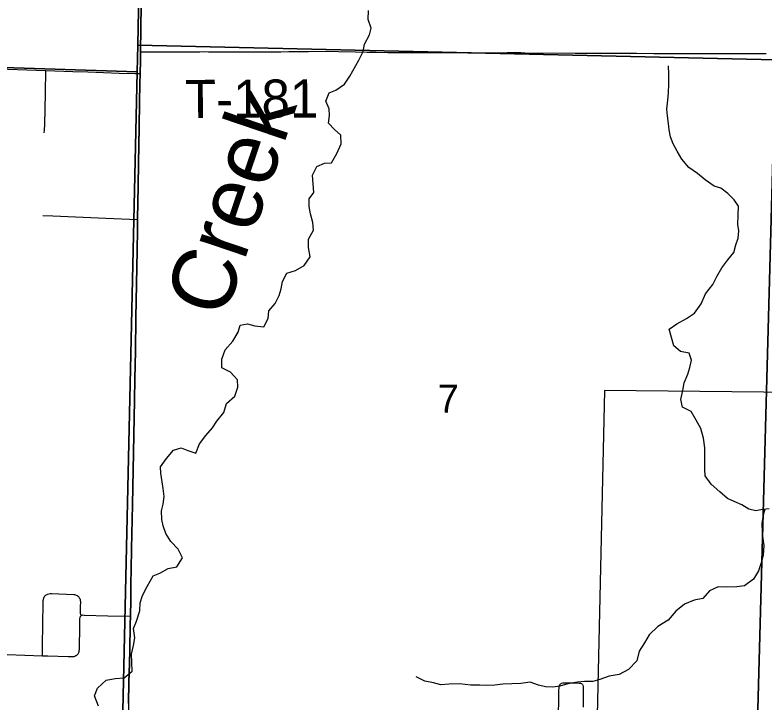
# Model space of a CAD drawing. Extents: x 0 to 34, y 0 to 22.
# Drawn here: x 5.615 to 6.731, y 18.619 to 19.643 of the extents above; entities that cross this region are included whole.
import ezdxf

# ---------------------------------------------------------------- set-up
doc = ezdxf.new("R2010")
doc.units = 0
for name, color, linetype in [('GM_X_Corporation', 7, 'Continuous'), ('GM_X_County_Road', 7, 'Continuous'), ('GM_X_Minor_River', 7, 'Continuous'), ('GM_X_Minor_River_Text', 7, 'Continuous'), ('GM_X_Section_Text', 7, 'Continuous'), ('GM_X_Township_Road', 7, 'Continuous'), ('GM_X_Township_Road_Text', 7, 'Continuous')]:
    doc.layers.add(name, color=color, linetype=linetype)

msp = doc.modelspace()

# ---------------------------------------------------------------- linework, layer by layer
at = {"layer": 'GM_X_Corporation'}
for points in [[(4.829, 20.5833), (5.8164, 20.5638), (5.7981, 19.5979), (5.7974, 19.5584), (4.8036, 19.5906)], [(5.8164, 20.5638), (6.788, 20.5454), (6.7486, 19.5865), (6.7472, 19.5762), (5.7981, 19.5979)], [(6.7472, 19.5762), (6.72, 18.5734), (5.7756, 18.586), (5.7974, 19.5584), (5.7981, 19.5979)], [(4.8036, 19.5906), (5.7974, 19.5584), (5.7756, 18.586), (5.7749, 18.5522), (4.7775, 18.5857)], [(6.7486, 19.5865), (7.7504, 19.5655), (7.7346, 18.5471), (6.72, 18.5734), (6.7472, 19.5762)]]:
    msp.add_lwpolyline(points, close=True, dxfattribs=at)
for points in [[(5.7845, 18.6185), (5.7851, 18.6508), (5.7858, 18.6782), (5.7862, 18.6987), (5.7867, 18.7359), (5.7871, 18.7491), (5.7877, 18.7725), (5.788, 18.7974), (5.7882, 18.8179), (5.7889, 18.849), (5.7901, 18.9142), (5.7933, 19.07), (5.7937, 19.1017), (5.7947, 19.1427), (5.7955, 19.1924), (5.7973, 19.2925), (5.7976, 19.3236), (5.7976, 19.3396), (5.7986, 19.3884), (5.7993, 19.4226), (5.8002, 19.4767), (5.8008, 19.5133), (5.8012, 19.5407), (5.8016, 19.5563), (5.8021, 19.5749), (5.8023, 19.5887), (5.8033, 19.6582)], [(5.8033, 19.6582), (5.8023, 19.5887), (5.8021, 19.5749), (5.8016, 19.5563), (5.8012, 19.5407), (5.8008, 19.5133), (5.8002, 19.4767), (5.7993, 19.4226), (5.7986, 19.3884), (5.7976, 19.3396), (5.7976, 19.3236), (5.7973, 19.2925), (5.7955, 19.1924), (5.7947, 19.1427), (5.7937, 19.1017), (5.7933, 19.07), (5.7901, 18.9142), (5.7889, 18.849), (5.7882, 18.8179), (5.788, 18.7974), (5.7877, 18.7725), (5.7871, 18.7491), (5.7867, 18.7359), (5.7862, 18.6987), (5.7858, 18.6782), (5.7851, 18.6508), (5.7845, 18.6185)], [(6.8851, 19.0796), (6.7293, 19.0817), (6.4924, 19.0846), (6.4812, 18.579)]]:
    msp.add_lwpolyline(points, dxfattribs=at)
at = {"layer": 'GM_X_County_Road'}
for points in [[(5.8025, 19.5881), (5.8035, 19.6576), (5.8043, 19.7024), (5.8052, 19.7639), (5.8058, 19.7975), (5.8061, 19.8255), (5.8063, 19.8478), (5.8071, 19.8907), (5.8076, 19.9268), (5.808, 19.9653), (5.8089, 20.0219), (5.8094, 20.0605), (5.8106, 20.1214), (5.8113, 20.1599), (5.8122, 20.1991), (5.813, 20.2432), (5.8138, 20.2811), (5.8144, 20.3128), (5.8159, 20.3769), (5.8167, 20.4278), (5.8179, 20.4919), (5.8193, 20.5613)], [(5.8018, 19.5558), (5.8023, 19.5743), (5.8025, 19.5881)], [(5.7979, 19.339), (5.7988, 19.3878), (5.7995, 19.422), (5.8005, 19.4761), (5.8011, 19.5128), (5.8014, 19.5401), (5.8018, 19.5558)], [(5.7874, 18.7485), (5.788, 18.772), (5.7882, 18.7968), (5.7885, 18.8173), (5.7891, 18.8484), (5.7903, 18.9136), (5.7935, 19.0695), (5.794, 19.1012), (5.7949, 19.1422), (5.7957, 19.1919), (5.7975, 19.2919), (5.7979, 19.323), (5.7979, 19.339)], [(5.6563, 18.6898), (5.6564, 18.6991), (5.6571, 18.7426), (5.6574, 18.7624), (5.6575, 18.7719), (5.6577, 18.7732), (5.6579, 18.7745), (5.6583, 18.7756), (5.6589, 18.777), (5.6601, 18.7787), (5.661, 18.7796), (5.6621, 18.7805), (5.6631, 18.7811), (5.6639, 18.7815), (5.6659, 18.782), (5.6678, 18.7822), (5.6698, 18.7821), (5.7028, 18.7811), (5.7042, 18.781), (5.7054, 18.7806), (5.7066, 18.7801), (5.7079, 18.7794), (5.709, 18.7786), (5.71, 18.7777), (5.7112, 18.776), (5.7118, 18.7748), (5.7122, 18.7735), (5.7125, 18.7719), (5.7128, 18.7703), (5.7126, 18.7627), (5.7125, 18.7531), (5.7127, 18.7517), (5.713, 18.7509), (5.7135, 18.75), (5.7138, 18.7494)], [(5.6563, 18.6898), (5.6643, 18.6896), (5.6947, 18.6885), (5.7003, 18.6885), (5.7017, 18.6885), (5.7034, 18.6888), (5.7047, 18.6892), (5.7062, 18.6899), (5.7074, 18.6906), (5.7083, 18.6916), (5.7093, 18.6927), (5.71, 18.6938), (5.7108, 18.6956), (5.7112, 18.6973), (5.7114, 18.6989), (5.7116, 18.7133), (5.7118, 18.7207), (5.7119, 18.7313), (5.7119, 18.7431), (5.712, 18.7447), (5.7123, 18.7466), (5.7126, 18.7476), (5.7132, 18.7486), (5.7138, 18.7494)], [(5.7138, 18.7494), (5.7149, 18.7501), (5.7156, 18.7503), (5.7169, 18.7504), (5.7184, 18.7503), (5.7538, 18.7493), (5.7874, 18.7485)], [(5.7843, 18.5826), (5.7844, 18.5925), (5.7847, 18.618), (5.7853, 18.6503), (5.7861, 18.6776), (5.7865, 18.6981), (5.787, 18.7354), (5.7874, 18.7485)], [(5.6014, 18.6915), (5.604, 18.6914), (5.6563, 18.6898)]]:
    msp.add_lwpolyline(points, dxfattribs=at)
at = {"layer": 'GM_X_Minor_River'}
for points in [[(6.1337, 19.5889), (6.1355, 19.5998), (6.143, 19.6133), (6.1456, 19.6235), (6.1409, 19.6361), (6.1416, 19.6498)], [(5.9231, 19.118), (5.9234, 19.1309), (5.9282, 19.1449), (5.9395, 19.1576), (5.9473, 19.1711), (5.9505, 19.1816), (5.9612, 19.1833), (5.9721, 19.1808), (5.9858, 19.1791), (5.9924, 19.1915), (5.993, 19.2028), (6.0024, 19.214), (6.0087, 19.2257), (6.0115, 19.2355), (6.0136, 19.2465), (6.0199, 19.2589), (6.0329, 19.2628), (6.0459, 19.2705), (6.0545, 19.2832), (6.0521, 19.2969), (6.052, 19.3095), (6.0594, 19.323), (6.0585, 19.3344), (6.0554, 19.347), (6.0533, 19.358), (6.0531, 19.3694), (6.0602, 19.3791), (6.0593, 19.3917), (6.058, 19.4046), (6.0647, 19.4178), (6.0762, 19.4225), (6.0864, 19.423), (6.0946, 19.4369), (6.1006, 19.4512), (6.1005, 19.4641), (6.0908, 19.4727), (6.0822, 19.4823), (6.0832, 19.4933), (6.083, 19.5032), (6.0779, 19.515), (6.0827, 19.5271), (6.0931, 19.5314), (6.1057, 19.5403), (6.1135, 19.5519), (6.1271, 19.5757), (6.1337, 19.5889)], [(6.7378, 18.9081), (6.7276, 18.9075), (6.718, 18.9051), (6.7075, 18.9076), (6.697, 18.9142), (6.6857, 18.919), (6.6755, 18.9237), (6.664, 18.9338), (6.6513, 18.9451), (6.6424, 18.9574), (6.6419, 18.9669), (6.6421, 18.9771), (6.6419, 18.9866), (6.6421, 18.9992), (6.6397, 19.0133), (6.6358, 19.0277), (6.6289, 19.04), (6.6215, 19.0531), (6.6088, 19.0594), (6.6063, 19.0712), (6.6093, 19.0844), (6.6114, 19.0958), (6.6165, 19.1086), (6.6198, 19.1188), (6.6223, 19.1297), (6.6187, 19.14), (6.6058, 19.1422), (6.5957, 19.1507), (6.5922, 19.1633), (6.589, 19.1755), (6.6002, 19.1837), (6.6144, 19.1914), (6.6266, 19.1995), (6.6364, 19.2133), (6.6431, 19.228), (6.654, 19.2422), (6.6599, 19.2539), (6.667, 19.267), (6.676, 19.279), (6.6853, 19.2898), (6.6881, 19.3011), (6.6917, 19.3109), (6.6923, 19.3219), (6.691, 19.3314), (6.6913, 19.3451), (6.6919, 19.3584), (6.6856, 19.368), (6.676, 19.3776), (6.6655, 19.3854), (6.6557, 19.3883), (6.6426, 19.398), (6.631, 19.4074), (6.6183, 19.416), (6.6076, 19.4287), (6.6006, 19.4406), (6.5947, 19.4514), (6.5908, 19.4617), (6.5887, 19.472), (6.5877, 19.4815), (6.5864, 19.4929), (6.5855, 19.5028), (6.5869, 19.5164), (6.5878, 19.527), (6.5885, 19.5399), (6.5884, 19.5551), (6.5879, 19.5676)], [(5.7398, 18.6149), (5.7336, 18.6302), (5.7384, 18.6415), (5.7511, 18.6534), (5.7644, 18.6558), (5.7777, 18.6567), (5.7897, 18.6667), (5.7895, 18.6796), (5.789, 18.6922), (5.7916, 18.705), (5.7937, 18.7164), (5.792, 18.7301), (5.7964, 18.741), (5.8013, 18.7564), (5.8015, 18.7686), (5.8051, 18.7795), (5.8122, 18.793), (5.8212, 18.8084), (5.8312, 18.8128), (5.8434, 18.8194), (5.8564, 18.8218), (5.8646, 18.8353), (5.8584, 18.8483), (5.8476, 18.8599), (5.8399, 18.8714), (5.8359, 18.8829), (5.8342, 18.8924), (5.8333, 18.9054), (5.8358, 18.9152), (5.8375, 18.9265), (5.8359, 18.9387), (5.8346, 18.9486), (5.8325, 18.9615), (5.832, 18.971), (5.8409, 18.9834), (5.8514, 18.9957), (5.8625, 18.9989), (5.8726, 18.9949), (5.8847, 18.9913), (5.8902, 19.0048), (5.8996, 19.0175), (5.9093, 19.0287), (5.9159, 19.0385), (5.9264, 19.0516), (5.9301, 19.0648), (5.9428, 19.0759), (5.9469, 19.0891), (5.9467, 19.1001), (5.9363, 19.1117), (5.9231, 19.118)], [(6.7312, 18.9077), (6.7289, 18.8988), (6.7268, 18.8863), (6.7273, 18.8738), (6.7282, 18.8639), (6.7296, 18.8536), (6.7285, 18.8392), (6.7264, 18.8294), (6.722, 18.8162), (6.7142, 18.8038), (6.7007, 18.7938), (6.6897, 18.7921), (6.6741, 18.7917), (6.6616, 18.7923), (6.649, 18.7865), (6.6389, 18.7749), (6.626, 18.7725), (6.6118, 18.7663), (6.5987, 18.756), (6.5875, 18.7425), (6.5718, 18.7334), (6.559, 18.7207), (6.5519, 18.7087), (6.5441, 18.6967), (6.5408, 18.6823), (6.5281, 18.6693), (6.5143, 18.662), (6.4998, 18.6592), (6.4857, 18.6546), (6.4754, 18.6514), (6.4629, 18.6512), (6.4526, 18.6503), (6.4381, 18.6479), (6.4263, 18.6447), (6.4157, 18.6431), (6.4047, 18.6437), (6.3945, 18.6461), (6.3821, 18.6506), (6.368, 18.6482), (6.3547, 18.6481), (6.3414, 18.6476), (6.3296, 18.6459), (6.3171, 18.6454), (6.3073, 18.646), (6.2936, 18.6458), (6.277, 18.6481), (6.2614, 18.6476), (6.2493, 18.6463), (6.2383, 18.6492), (6.2255, 18.6521), (6.2123, 18.6584)]]:
    msp.add_lwpolyline(points, dxfattribs=at)
at = {"layer": 'GM_X_Township_Road'}
for points in [[(4.8051, 19.5918), (4.8345, 19.5909), (4.891, 19.5887), (4.9184, 19.5877), (4.9855, 19.585), (5.0581, 19.5818), (5.1041, 19.5801), (5.1426, 19.5787), (5.1737, 19.5777), (5.2054, 19.5765), (5.2817, 19.5738), (5.3352, 19.5717), (5.401, 19.5697), (5.4955, 19.5668), (5.6048, 19.5625), (5.6615, 19.5604)], [(5.8018, 19.5558), (5.8023, 19.5743), (5.8025, 19.5881)], [(5.8025, 19.5881), (5.807, 19.5881), (5.8093, 19.5881), (5.8128, 19.5882), (5.8182, 19.5882), (5.8236, 19.5883), (5.8318, 19.5884), (5.8425, 19.5884), (5.8516, 19.5884), (5.8663, 19.5883), (5.8749, 19.5883), (5.883, 19.5883), (5.8903, 19.5883), (5.8964, 19.5885), (5.9036, 19.5883), (5.9115, 19.5883), (5.9201, 19.5884), (5.9287, 19.5884), (5.9361, 19.5884), (5.9486, 19.5882), (5.9611, 19.5884), (5.9701, 19.5882), (5.9793, 19.5884), (5.9988, 19.5884), (6.0111, 19.5884), (6.0227, 19.5886), (6.0337, 19.5887), (6.052, 19.5888), (6.0779, 19.5891), (6.097, 19.5888), (6.1222, 19.5883), (6.1396, 19.5878), (6.1527, 19.5876), (6.1701, 19.5874), (6.1893, 19.5872), (6.2011, 19.5871), (6.2103, 19.587), (6.2364, 19.5871), (6.2563, 19.5871), (6.2893, 19.5869), (6.3291, 19.5869), (6.3477, 19.587), (6.3682, 19.587), (6.3744, 19.5869), (6.449, 19.5861), (6.4875, 19.5862), (6.5404, 19.586), (6.5659, 19.5859), (6.6057, 19.5857), (6.6343, 19.5855), (6.6647, 19.5856), (6.7051, 19.5855), (6.7331, 19.5858)], [(5.659, 19.4676), (5.6595, 19.4719), (5.6598, 19.48), (5.6607, 19.5267), (5.6615, 19.5604)], [(5.6615, 19.5604), (5.7016, 19.5592), (5.724, 19.5586), (5.7706, 19.5567), (5.7943, 19.556), (5.8018, 19.5558)], [(5.6569, 19.3448), (5.6719, 19.344), (5.7508, 19.3406), (5.7979, 19.339)], [(6.4242, 18.5993), (6.4248, 18.6272), (6.4249, 18.6366), (6.4252, 18.6434), (6.4255, 18.6452), (6.426, 18.6464), (6.4267, 18.6474), (6.4276, 18.6481), (6.4287, 18.6487), (6.4305, 18.6492), (6.4336, 18.6495), (6.4511, 18.6493), (6.4548, 18.6491), (6.4567, 18.6488), (6.4584, 18.6482), (6.4598, 18.647), (6.4604, 18.6459), (6.4609, 18.6442), (6.4611, 18.641), (6.461, 18.633), (6.4608, 18.6243), (6.4607, 18.613)]]:
    msp.add_lwpolyline(points, dxfattribs=at)

# ---------------------------------------------------------------- texts
at = {"layer": 'GM_X_Minor_River_Text'}
msp.add_text('Creek', height=0.09478, rotation=71.2685, dxfattribs=at).set_placement((5.927, 19.1889))
at = {"layer": 'GM_X_Section_Text'}
msp.add_text('7', height=0.0419, rotation=0, dxfattribs=at).set_placement((6.2446, 19.0513))
at = {"layer": 'GM_X_Township_Road_Text'}
msp.add_text('T-181', height=0.05682, rotation=0.2682, dxfattribs=at).set_placement((5.8684, 19.4896))

doc.saveas('drawing.dxf')
